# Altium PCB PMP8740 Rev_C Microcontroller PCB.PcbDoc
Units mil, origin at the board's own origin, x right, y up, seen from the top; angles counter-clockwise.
Board outline 1780 x 1140 mil, 4 copper layers (Top Layer, MidLayer1, MidLayer2, Bottom Layer), stack 90 mil thick; 19 components, 37 nets, 112 pads, 52 vias.
Unrouted connection lines stored in the file: 1.
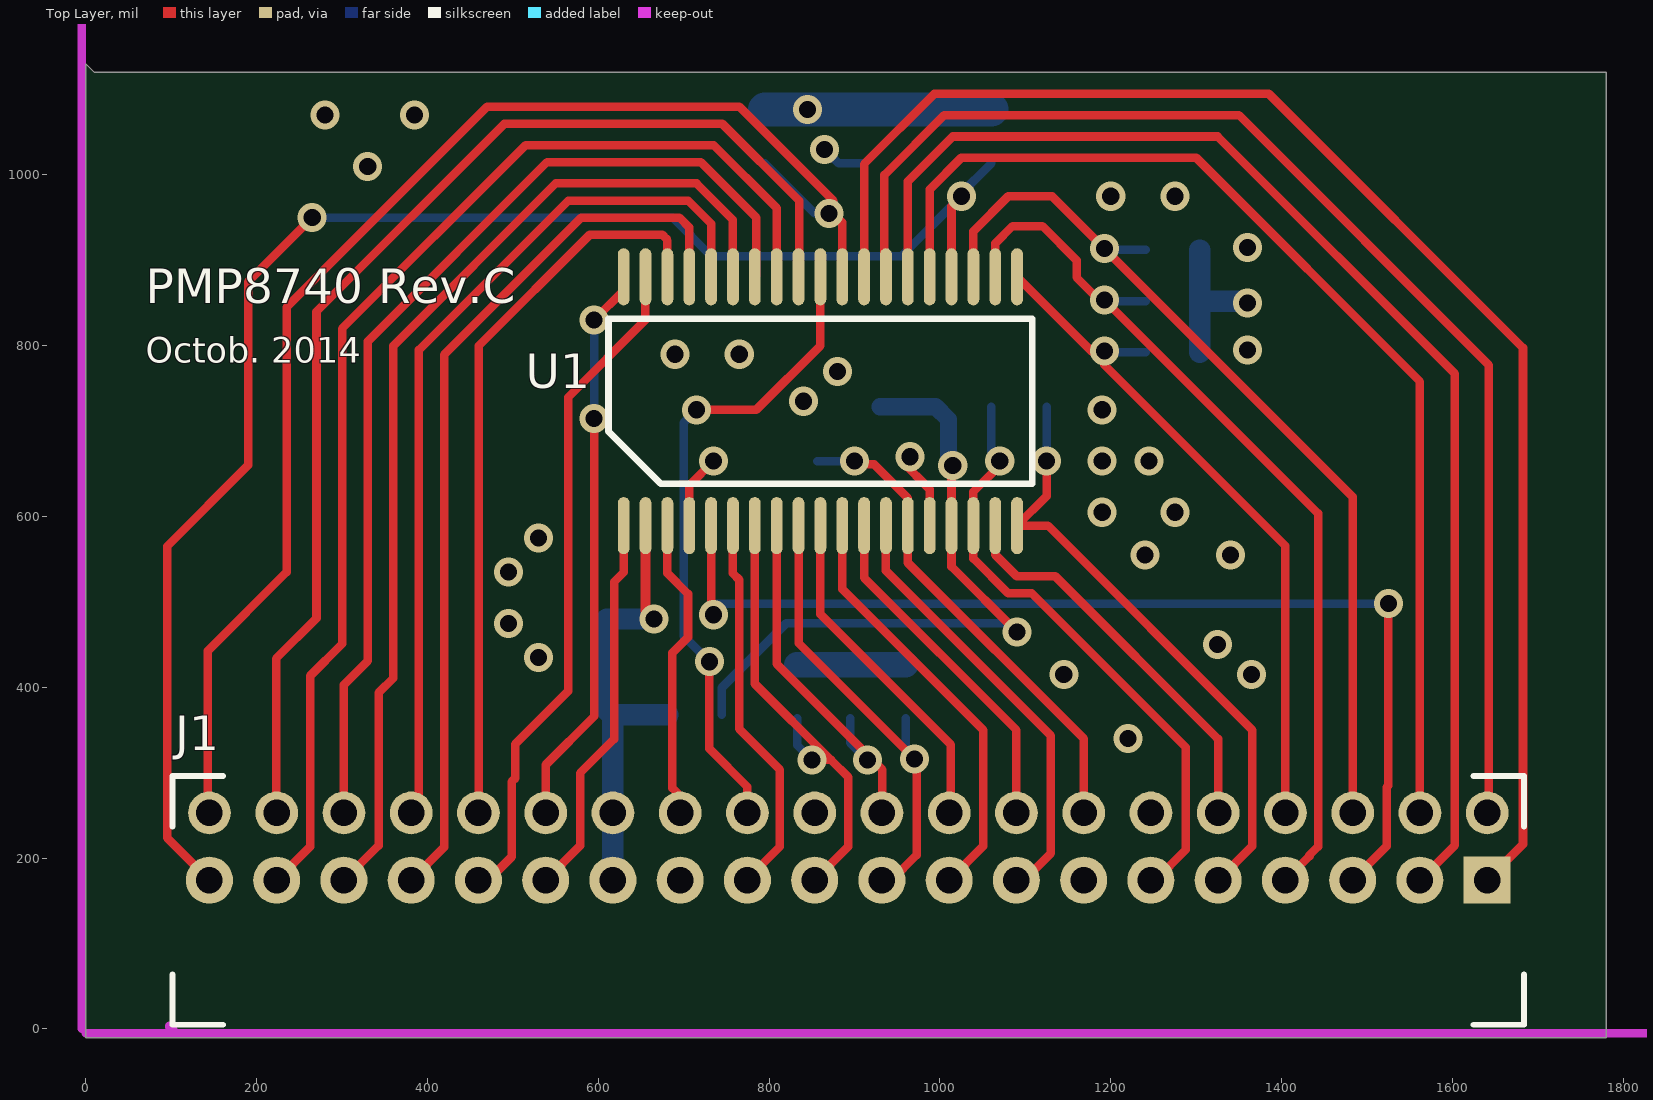
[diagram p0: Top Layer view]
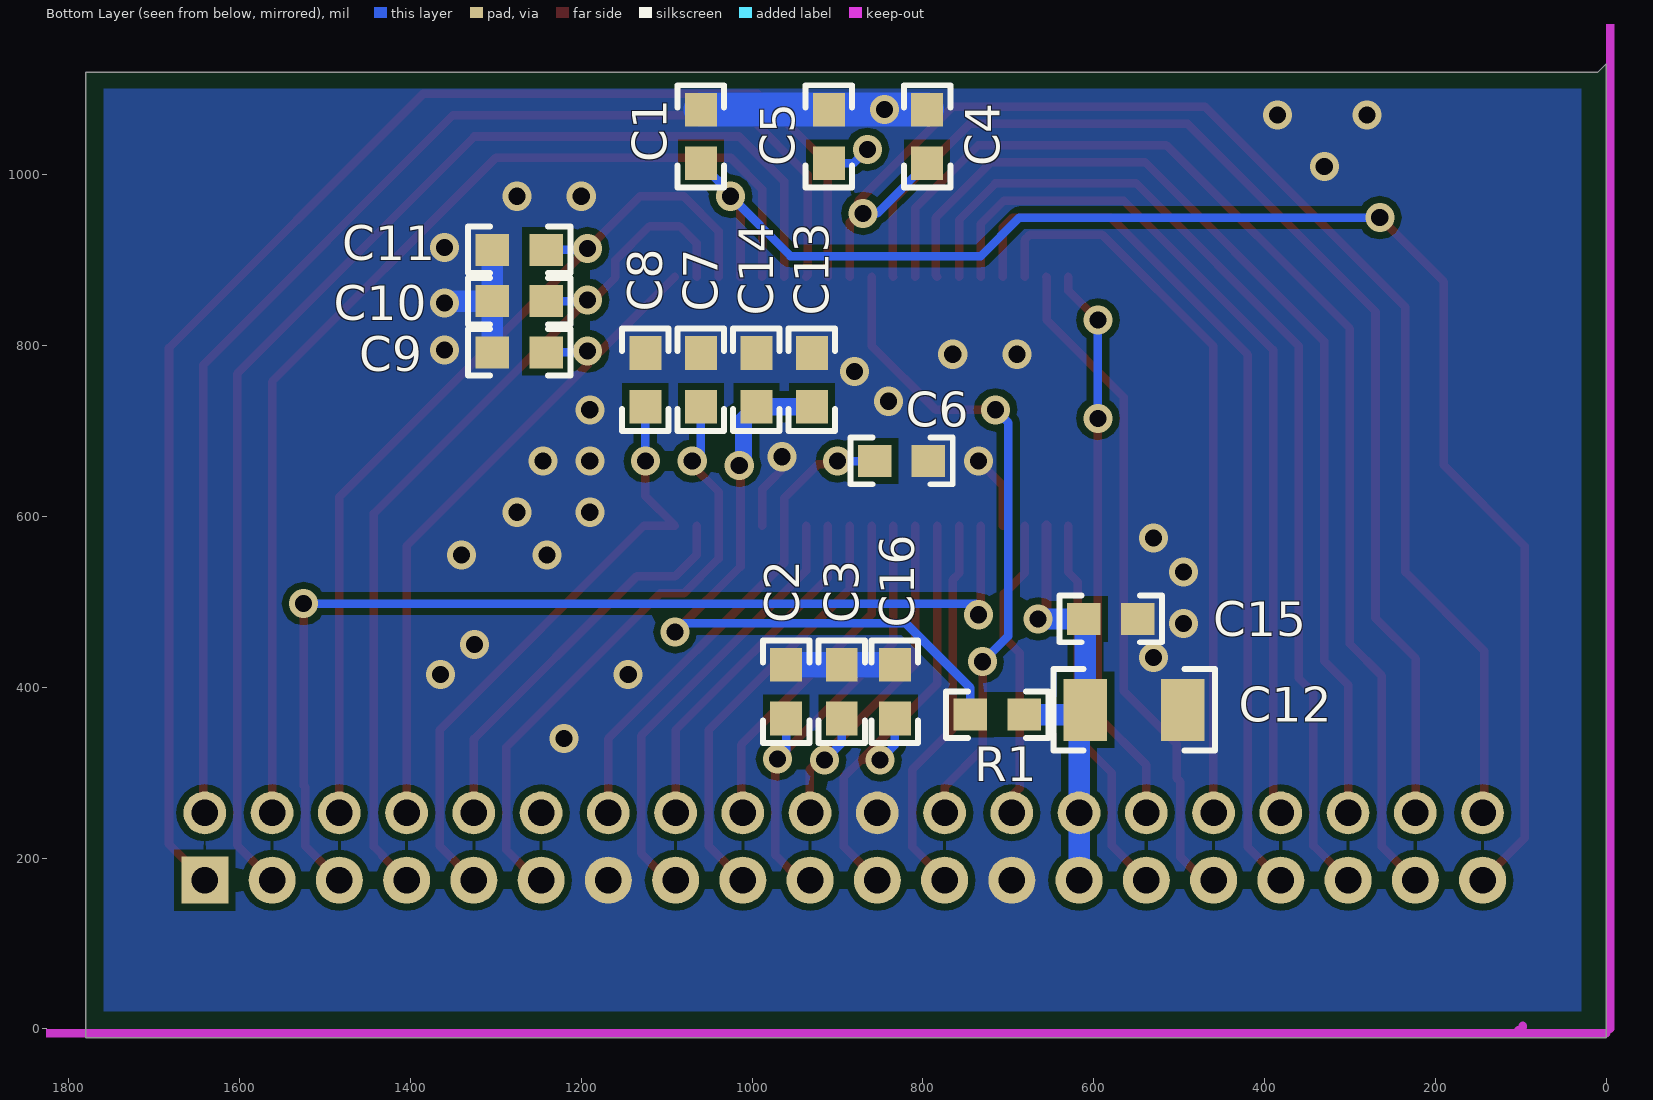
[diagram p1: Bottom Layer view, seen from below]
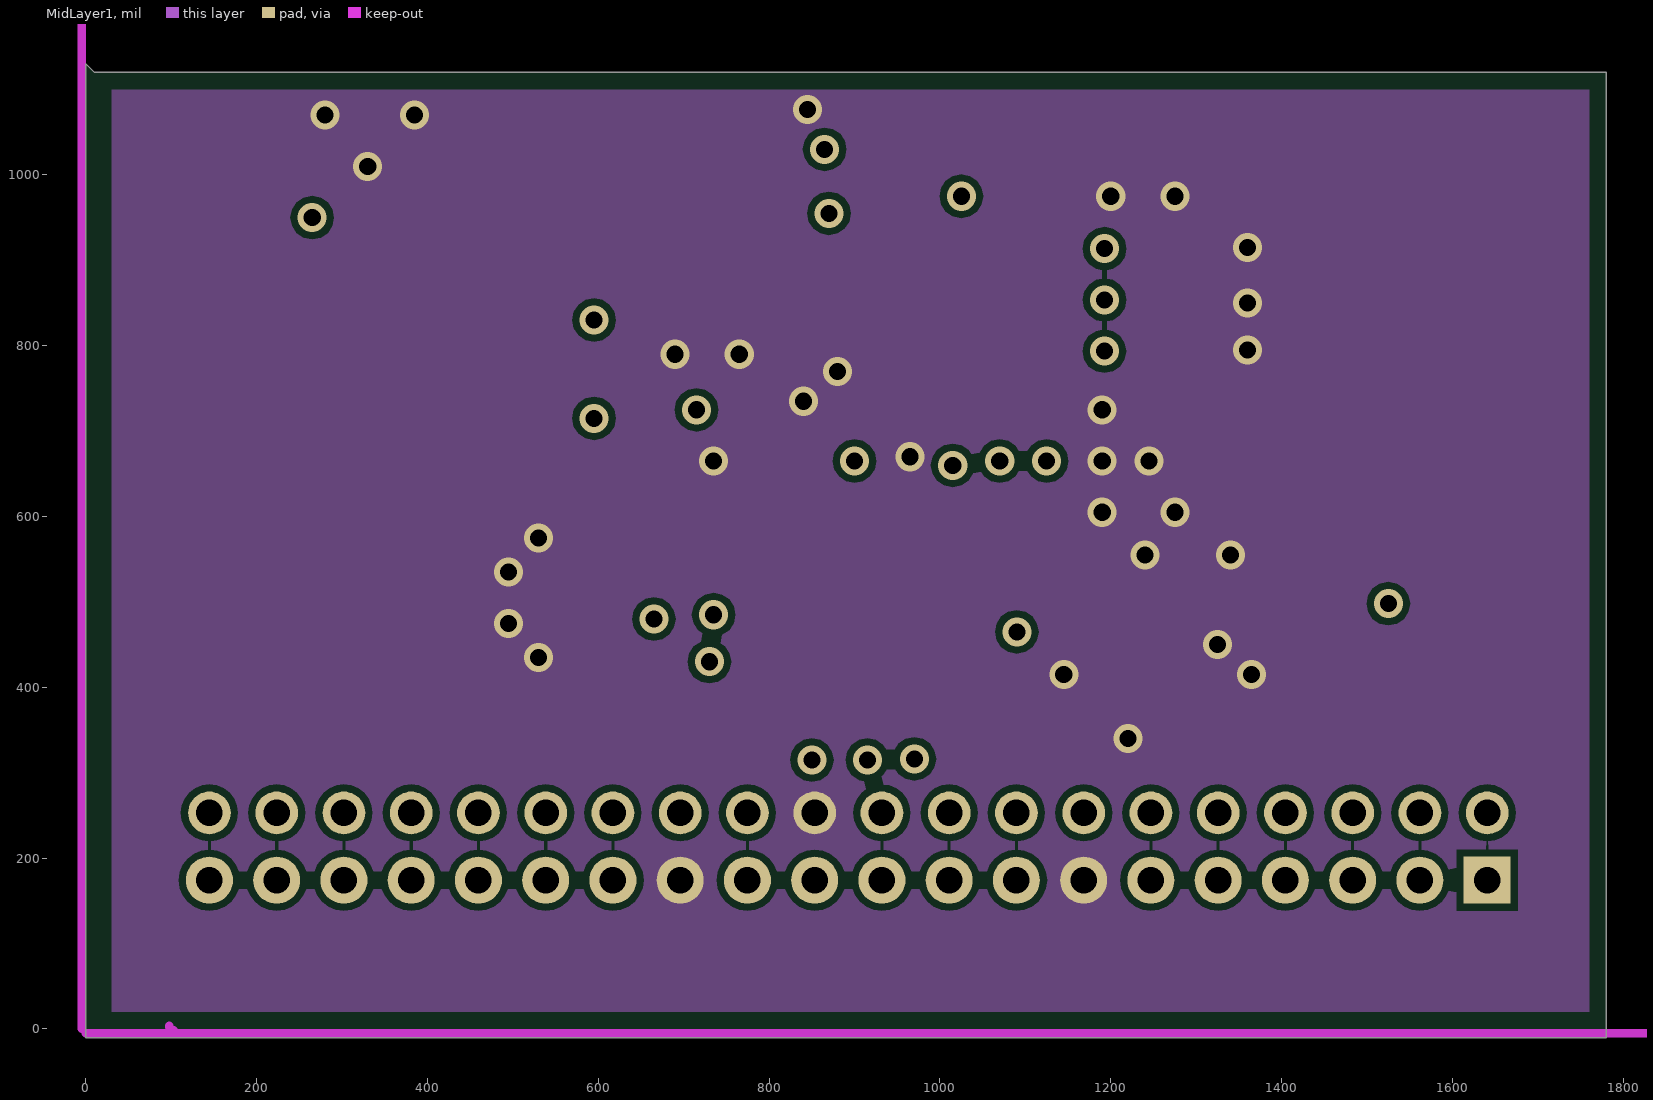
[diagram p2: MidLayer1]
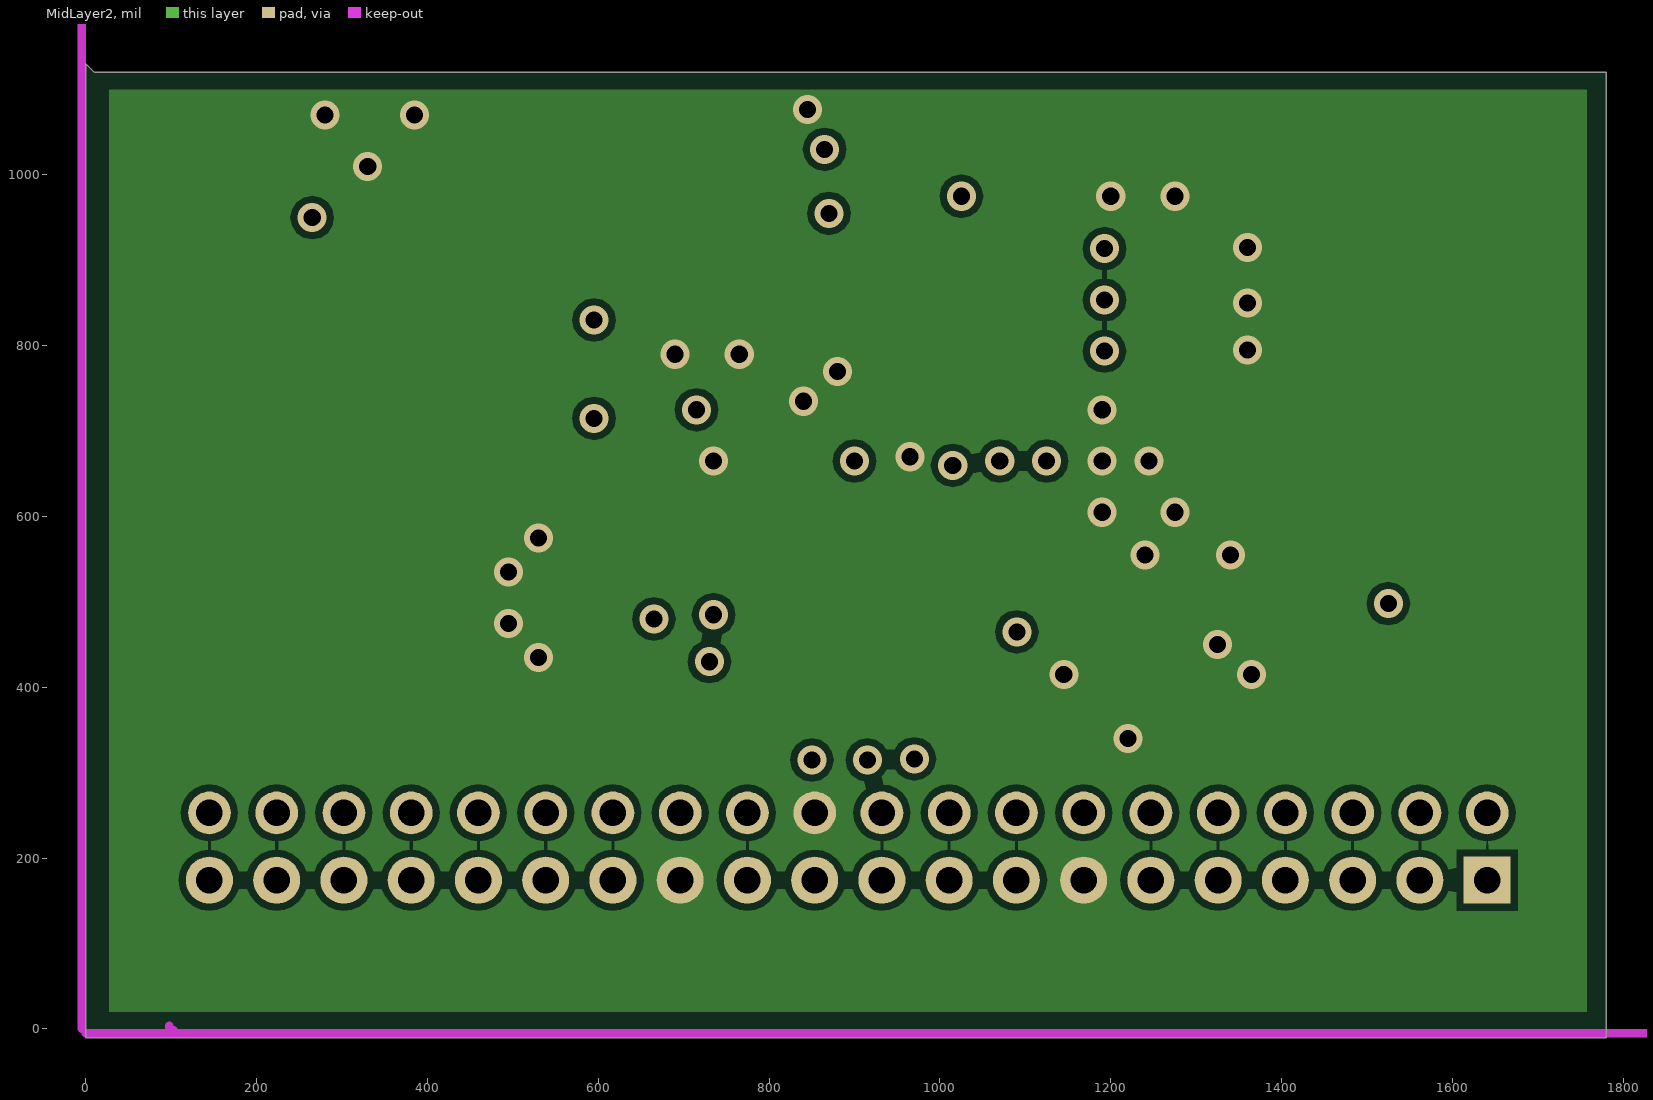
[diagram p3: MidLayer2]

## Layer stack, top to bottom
Top Layer: signal copper 1.4
Dielectric: prepreg 59.2, FR-4, Dk 4.8
MidLayer1: signal copper 1.4
Dielectric: core 12.6, FR-4, Dk 4.8
MidLayer2: signal copper 1.4
Dielectric: prepreg 12.6, FR-4, Dk 4.8
Bottom Layer: signal copper 1.4

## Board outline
0,1130 10,1120 1780,1120 1780,-10 0,-10

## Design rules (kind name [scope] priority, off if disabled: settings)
AcuteAngle [All] p1: minimum=4.50000000000000E+0001 checktracksonly=FALSE
AssemblyTestPointUsage [All] p1: valid=2
Clearance Clearance_3 [InNamedPolygon('Mid Layer 2 ground plane')] p1: gap=8
Clearance Clearance_2 [InNamedPolygon('Mid Layer 1 ground plane')] p2: gap=8
Clearance Clearance_1 [InNamedPolygon('Bottom layer ground plane')] p3: gap=8
Clearance "Clearance for GND" [InNamedPolygon('MidLayer1-No Net')] p4: gap=8
Clearance Clearance_BoardEdge_MountingHoles [OnCopper and InComponentClass('Mounting Holes') vs IsKeepOut] p5: gap=40
Clearance Clearance_BoardEdge_Poly [OnCopper and InPoly vs IsKeepOut] p6: gap=25
Clearance Clearance_BoardEdge [OnCopper and Not InComponentClass('Logo') and not InComponentClass('FiducialMark') and not InRegion(1000,500,4000,800) and Not IsKeepout vs IsKeepOut] p7: gap=75
Clearance Clearance_Poly [InPolygon] p8: gap=25
Clearance [All] p9: gap=8
ComponentClearance ComponentClearance_Logo [InComponentClass('Logo')] p1: gap=50 collisioncheckmode=3 verticalgap=10 showdistances=FALSE
ComponentClearance ComponentClearance_ScrewToNut [(HasFootprint('NY PMS 440 0025 PH')) vs (HasFootprint('Keystone_1902C'))] p2: gap=5 collisioncheckmode=3 verticalgap=10 showdistances=FALSE
ComponentClearance ComponentClearance_MountingHoles [InComponentClass('Mounting Holes')] p3: gap=250 collisioncheckmode=3 verticalgap=100000 showdistances=FALSE
ComponentClearance ComponentClearance_SmallPassives [HasFootprint('0201*') or HasFootprint('0402*') or HasFootprint('0508') or HasFootprint('0603*') or HasFootprint('0612') or HasFootprint('0805*') or HasFootprint('0815*') or HasFootprint('0830*') or HasFootprint('1206*') or HasFootprint('1210*') or HasFootprint('1808*') or HasFootprint('1812*') or HasFootprint('1825*') or HasFootprint('2010*') or HasFootprint('2220*') or HasFootprint('2225*') or HasFootprint('2512*') or HasFootprint('2728*') or HasFootprint('3518*') vs HasFootprint('0201*') or HasFootprint('0402*') or HasFootprint('0508') or HasFootprint('0603*') or HasFootprint('0612') or HasFootprint('0805*') or HasFootprint('0815*') or HasFootprint('0830*') or HasFootprint('1206*') or HasFootprint('1210*') or HasFootprint('1808*') or HasFootprint('1812*') or HasFootprint('1825*') or HasFootprint('2010*') or HasFootprint('2220*') or HasFootprint('2225*') or HasFootprint('2512*') or HasFootprint('2728*') or HasFootprint('3518*')] p4: gap=20 collisioncheckmode=3 verticalgap=10 showdistances=FALSE
ComponentClearance ComponentClearance_THtoSMT [IsThruComponent vs IsSMTComponent] p5: gap=100 collisioncheckmode=3 verticalgap=30 showdistances=FALSE
ComponentClearance ComponentClearance_THtoTH [IsThruComponent vs IsThruComponent] p6: gap=118.11 collisioncheckmode=3 verticalgap=30 showdistances=FALSE
ComponentClearance [All] p7: gap=40 collisioncheckmode=3 verticalgap=10 showdistances=FALSE
DiffPairsRouting [All] p1: maxlimit=100 minlimit=10 mostfreqgap=10 maxuncoupledlength=1000
FabricationTestPointUsage TestPointUsage [All] p1: valid=2 allowmultiple=FALSE
FabricationTestpoint Testpoint [All] p1: side=3 testpointundercomponent=TRUE minsize=40 maxsize=100 preferedsize=60 minholesize=0 maxholesize=40 preferedholesize=32 testpointgrid=1 allowsidetop=TRUE allowsidebottom=TRUE usegrid=TRUE gridtolerance=0.01
FanoutControl Fanout_LCC [IsLCC] p1: bgadir=Out bgaviamode=Centered fanoutstyle=Auto fanoutdirection=Alternating viagrid=1 // Fanout_LCC (Default Rule)
FanoutControl Fanout_BGA [IsBGA] p2: bgadir=Out bgaviamode=Centered fanoutstyle=Auto fanoutdirection=Alternating viagrid=1 // Fanout_BGA (Default Rule)
FanoutControl Fanout_Default [All] p4: bgadir=Out bgaviamode=Centered fanoutstyle=Auto fanoutdirection=Alternating viagrid=1 // Fanout_Default (Default Rule)
FanoutControl Fanout_Small [(CompPinCount < 5)] p5: bgadir=Out bgaviamode=Centered fanoutstyle=Auto fanoutdirection=OutThenIn viagrid=1 // Fanout_Small (Default Rule)
HoleSize [All] p1: absolutevalues=TRUE maxlimit=251 minlimit=8 maxpercent=80.000 minpercent=20.000
MinimumAnnularRing MinimumAnnularRing_ThermalPadVias [IsVia and InAnyComponent] p1: minimumring=5.91
MinimumAnnularRing [All] p2: minimumring=9
MinimumSolderMaskSliver MinimumSolderMaskSliver_Logo [InComponentClass('Logo') vs InComponentClass('Logo')] p1: minsoldermaskwidth=0.7
MinimumSolderMaskSliver [All] p2: minsoldermaskwidth=3.94
PlaneConnect [All] p1: planeconnectstyle=Relief reliefexpansion=10 reliefentries=4 reliefconductorwidth=10 reliefairgap=10
PolygonConnect PolygonConnect_6 [All vs IsNamedPolygon('Mid Layer 2 ground plane')] p1: connectstyle=Direct reliefconductorwidth=10 reliefentries=4 polygonreliefangle="90 Angle" airgapwidth=10
PolygonConnect PolygonConnect_5 [All vs IsNamedPolygon('Mid Layer 1 ground plane')] p2: connectstyle=Direct reliefconductorwidth=10 reliefentries=4 polygonreliefangle="90 Angle" airgapwidth=10
PolygonConnect PolygonConnect_4 [All vs IsNamedPolygon('Bottom layer ground plane')] p3: connectstyle=Direct reliefconductorwidth=10 reliefentries=4 polygonreliefangle="90 Angle" airgapwidth=10
PolygonConnect PolygonConnect_3 [All vs IsNamedPolygon('MidLayer1-No Net')] p4: connectstyle=Direct reliefconductorwidth=10 reliefentries=4 polygonreliefangle="90 Angle" airgapwidth=10
PolygonConnect PolygonConnect_2 [All vs IsNamedPolygon('MidLayer1-No Net')] p5: connectstyle=Direct reliefconductorwidth=10 reliefentries=4 polygonreliefangle="90 Angle" airgapwidth=10
PolygonConnect PolygonConnect_1 [All vs IsNamedPolygon('MidLayer1-No Net')] p6: connectstyle=Direct reliefconductorwidth=10 reliefentries=4 polygonreliefangle="90 Angle" airgapwidth=10
PolygonConnect [All] p7: connectstyle=Relief reliefconductorwidth=10 reliefentries=4 polygonreliefangle="90 Angle" airgapwidth=10
RoomDefinition "PMP8740 Rev_C 2KW BC Microcontroller Schematic" [InComponentClass('PMP8740 Rev_C 2KW BC Microcontroller Schematic')] p1: confinementstyle=ConfineIn formatcopy=TRUE lockcomponents=FALSE outline 4998,76 8798,76 8798,1756 4998,1756
RoutingVias ThermalPadVias [IsVia and InAnyComponent] p1: holewidth=7.87 width=19.68 viastyle="Through Hole" minholewidth=7.87 minwidth=19.68 maxholewidth=12.99 maxwidth=23.62
RoutingVias [All] p2: holewidth=16 width=34 viastyle="Through Hole" minholewidth=16 minwidth=34 maxholewidth=16 maxwidth=34
SMDToCorner [All] p1: distance=30000
SilkToSilkClearance [All] p1: silktosilkclearance=5
SilkscreenOverComponentPads [All] p1: minsilkscreentomaskgap=5
SolderMaskExpansion [All] p1: expansion=1.97
Width [All] p1: maxlimit=100 minlimit=6 preferedwidth=10 checkconnectedcopper=TRUE
14 further rules are at their usual default settings.

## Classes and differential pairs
component class "PMP8740 Rev_C 2KW BC Microcontroller Schematic": C1 C2 C3 C4 C5 C6 C8 C9 C10 C11 C12 C13 C14 C15 C16 J1 R1 U1

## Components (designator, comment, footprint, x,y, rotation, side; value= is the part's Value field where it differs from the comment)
C1 "C1608X7R1H104K" 0603 1060,1045 r90 bottom
C2 "C1608X7R1H473K" 0603 960,395 r90 bottom
C3 "C1608X7R1H104K" 0603 895,395 r90 bottom
C4 "C1608X7R1E105K080AB" 0603 795,1045 r90 bottom
C5 "C1608X7R1H104K" 0603 910,1045 r90 bottom
C6 "C1608X7R1H104K" 0603 825,665 r180 bottom
C7 "C1608X7R1H103K" 0603 1060,760 r90 bottom
C8 "C1608X7R1H103K" 0603 1125,760 r90 bottom
C9 "C1608X7R1H103K" 0603 1272.68,792.16 r0 bottom
C10 "C1608X7R1H103K" 0603 1272.68,852.16 r0 bottom
C11 "C1608X7R1H103K" 0603 1272.68,912.16 r0 bottom
C12 "C3216X7R1A106M" 1206 552.68,373.61 r180 bottom
C13 "C1608X7R1E105K080AB" 0603 930,760 r90 bottom
C14 "C1608X7R1H104K" 0603 995,760 r90 bottom
C15 "C1608X7R1H104K" 0603 580,480 r180 bottom
C16 "C1608C0G1H102J" 0603 832.68,395 r90 bottom
J1 "NPPN202FJFN-RC" HEADER_NPPN202FJFN-RC 892.68,213.61 r0 top
R1 "CRCW060333R2FKEA" 0603 713,368 r180 bottom
U1 "MSP430F2252TDA" DA0038A_N 860,735 r90 top

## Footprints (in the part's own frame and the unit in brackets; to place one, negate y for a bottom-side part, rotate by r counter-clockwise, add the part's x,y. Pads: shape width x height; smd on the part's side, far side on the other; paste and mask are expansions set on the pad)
0603 [mm] "0603 from SM-752 data"
  rect 1x0.95 smd: 1(-0.8,0) 2(0.8,0)
  silkscreen extent -1.52,-0.69 1.52,0.69, body extent -0.87,-0.47 0.87,0.47, height 0.85
1206 [mm] "1206 from SM-752 data"
  rect 1.3x1.85 smd: 1(-1.45,0) 2(1.45,0)
  silkscreen extent -2.4,-1.21 2.4,1.21, body extent -1.7,-0.9 1.7,0.9, height 1.35
DA0038A_N [mm] "TSOP, 38-Leads, Body 12.6x6.2mm (max), Pitch 0.65mm, IPC Medium Density"
  oval 1.7x0.35 smd: 1(-3.7,5.85) 2(-3.7,5.2) 3(-3.7,4.55) 4(-3.7,3.9) 5(-3.7,3.25) 6(-3.7,2.6) 7(-3.7,1.95) 8(-3.7,1.3) 9(-3.7,0.65) 10(-3.7,0) 11(-3.7,-0.65) 12(-3.7,-1.3) 13(-3.7,-1.95) 14(-3.7,-2.6) 15(-3.7,-3.25) 16(-3.7,-3.9) 17(-3.7,-4.55) 18(-3.7,-5.2) 19(-3.7,-5.85) 20(3.7,-5.85) 21(3.7,-5.2) 22(3.7,-4.55) 23(3.7,-3.9) 24(3.7,-3.25) 25(3.7,-2.6) 26(3.7,-1.95) 27(3.7,-1.3) 28(3.7,-0.65) 29(3.7,0) 30(3.7,0.65) 31(3.7,1.3) 32(3.7,1.95) 33(3.7,2.6) 34(3.7,3.25) 35(3.7,3.9) 36(3.7,4.55) 37(3.7,5.2) 38(3.7,5.85)
  silkscreen extent -2.45,-6.3 2.45,6.3, body extent -4.17,-6.3 4.11,6.3, height 1.2
HEADER_NPPN202FJFN-RC [mm] "Sullins, Header 20x2 ,2mm Pitch"
  rect 1.4x1.4 hole 0.787: 1(19,-1)
  round 1.27 hole 0.787: 2(19,1) 4(17,1) 6(15,1) 8(13,1) 10(11,1) 12(9,1) 14(7,1) 16(5,1) 18(3,1) 20(1,1) 22(-1,1) 24(-3,1) 26(-5,1) 28(-7,1) 30(-9,1) 32(-11,1) 34(-13,1) 36(-15,1) 38(-17,1) 40(-19,1)
  round 1.4 hole 0.787: 3(17,-1) 5(15,-1) 7(13,-1) 9(11,-1) 11(9,-1) 13(7,-1) 15(5,-1) 17(3,-1) 19(1,-1) 21(-1,-1) 23(-3,-1) 25(-5,-1) 27(-7,-1) 29(-9,-1) 31(-11,-1) 33(-13,-1) 35(-15,-1) 37(-17,-1) 39(-19,-1)
  silkscreen extent -20.1,-5.3 20.1,2.1, body extent -20.06,-5.26 20.06,2.06, height 4.92

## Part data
C1 C3 C5 C6 C14 C15: "CAP, CERM, 0.1uF, 50V, +/-10%, X7R, 0603"
C2: "CAP, CERM, 0.047 µF, 50 V, +/- 10%, X7R, 0603"
C4 C13: "CAP, CERM, 1uF, 25V, +/-10%, X7R, 0603"
C7 C8 C9 C10 C11: "CAP, CERM, 0.01uF, 50V, +/-10%, X7R, 0603"
C12: "CAP, CERM, 10uF, 10V, +/-20%, X7R, 1206"
C16: "CAP, CERM, 1000pF, 50V, +/-5%, C0G/NP0, 0603"
J1: "Receptacle, 2mm, 20x2, R/A, TH"
R1: "RES, 33.2 ohm, 1%, 0.1W, 0603"
U1: "MIXED SIGNAL MICROCONTROLLER, DA0038A"

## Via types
v1: diameter 34, hole 20, Top Layer to Bottom Layer, 52 vias

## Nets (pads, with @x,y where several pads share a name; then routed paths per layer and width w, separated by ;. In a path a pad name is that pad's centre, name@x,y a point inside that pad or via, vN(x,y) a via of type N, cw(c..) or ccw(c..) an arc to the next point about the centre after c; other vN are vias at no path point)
+3V45: C12.1 C15.1 J1.27 J1.28 R1.2 U1.2 | length 541.5
  Top Layer w12: U1.2 655.28,489.72 v1(665,480)
  Bottom Layer w25: C15.1@609.77,479.77 C12.1 C12.1@615.38,368 ; C15.1 v1(665,480) ; J1.27 J1.28 617.09,366.29 C12.1@615.38,368 ; R1.2 C12.1@615.38,368
"BACKLIGHT P1.0": J1.37 U1.31 | length 1386.5
  Top Layer w10: J1.37 262.68,213.54 262.68,413.61 300,450.93 300,820 515,1035 735,1035 808.82,961.18 U1.31
"CLOCK TEST/SBWTCK": J1.29 U1.1 | length 453.2
  Top Layer w10: J1.29 578.68,214.57 578.68,299.61 618.43,339.36 618.43,523.43 630,535 630,589.02 U1.1
"D4(D0) P1.7": J1.30 U1.38 | length 665.5
  Top Layer w10: J1.30 538.35,309.28 595,365.93 v1(595,715) ; v1(595,830) 629.68,864.68 U1.38
  Bottom Layer w10: v1(595,715) v1(595,830)
"D5(D1) P1.6": J1.31 U1.37 | length 794.3
  Top Layer w10: J1.31 471.31,174.24 498.68,201.61 498.68,289.61 502.68,293.61 502.68,333.61 564.53,395.47 564.53,739.53 655,830 655,880.39 U1.37
"D6(D2) P1.5": J1.32 U1.36 | length 867.8
  Top Layer w10: J1.32 460.16,253.54 460.16,800.16 590,930 675,930 680,925 680,923.98 680.87,923.11 U1.36
"D7(D3) P1.4": J1.33 U1.35 | length 1047.3
  Top Layer w10: J1.33 419.68,213.05 419.68,789.68 580,950 695,950 706.46,938.54 U1.35
"DATA_I/O RST/NMI": C16.1 J1.21 U1.7 | length 554.9
  Top Layer w10: U1.7 783.23,404.31 872.53,315 ; v1(850,315) 872.53,315 ; J1.21 892.68,213.61 892.68,294.85 872.53,315
  Bottom Layer w10: C16.1 832.68,332.32 v1(850,315)
"E P1.3": J1.34 U1.34 | length 1031.3
  Top Layer w10: J1.34@382.68,254.79 390,262.11 390,795 565,970 705,970 732.05,942.95 U1.34
"ENA_FB P4.7": J1.4 U1.24 | length 1305.2
  Top Layer w10: U1.24 987.95,982.95 1025,1020 1300,1020 1561.97,758.03 J1.4
GND-S: C1.2 C2.2 C3.2 C4.2 C5.2 C6.2 C7.2 C8.2 C9.2 C10.2 C11.2 C12.2 C13.2 C14.2 C15.2 C16.2 J1.13 J1.22 J1.25 U1.4 U1.15 | length 757.9
  Top Layer w10: U1.4 706.46,636.46 v1(735,665) ; v1@965,660 960,665 955,665 987.95,632.05 U1.15
  Bottom Layer w25: C9.2 C10.2 ; C11.2 C10.2 ; v1(1360,850) 1357.84,852.16 C10.2
  Bottom Layer w30: C16.2 C3.2 C2.2
  Bottom Layer w40: C4.2 C5.2 C1.2
  other v1: 1220,340 1145,415 1365,415 530,435 1325,450 495,475 495,535 1240,555 1340,555 530,575 1190,605 1275,605 1190,665 1245,665 965,670 1190,725 840.31,735 880,770 690,790 765,790 1360,795 1360,915 1200,975 1275,975 330,1010 280,1070 385,1070 845,1076.5
"INRUSH_RELAY P2.6": J1.23 U1.6 | length 453.7
  Top Layer w10: U1.6 757.64,533.36 765,526 765,351.29 812.68,303.61 812.68,213.61 774.57,175.5 J1.23
"IOUT FB P3.7": C4.1 J1.40 U1.28 | length 1590.4
  Top Layer w10: J1.40 142.68,254.95 142.68,442.68 235,535 235,845 470,1080 765,1080 875,970 875,955 885.59,944.41 U1.28
  Bottom Layer w10: C4.1 v1@853.5,955
  other v1: 870,955
"LED_GREEN P3.0": J1.17 U1.11 | length 500
  Top Layer w10: U1.11 885.59,515.09 1050.68,350 1050.68,214.13 J1.17
"LED_RED P3.2": J1.15 U1.13 | length 516.8
  Top Layer w10: U1.13 936.77,536.5 1129.68,343.59 1129.68,205.61 1098.31,174.24 J1.15
"LED_YELLOW P3.1": J1.16 U1.12 | length 410.2
  Top Layer w10: U1.12 911.18,528.35 1089.53,350 J1.16
NetC13_1: C13.1 C14.1 R1.1 U1.16 | length 795.9
  Top Layer w10: v1@1005,665 1010,660 v1(1015,660) ; v1@1013.54,660 U1.16 1013.54,541.46 v1(1090,465)
  Bottom Layer w10: R1.1 744.5,399.5 820,475 1080,475 v1(1090,465)
  Bottom Layer w20: C13.1 C14.1 1010,713.5 1010,660 v1(1015,660)
P2.7: J1.5 U1.5 | length 1246.6
  Top Layer w10: v1@732.05,485 U1.5 ; J1.5 1523,214.01 1523,283 1525,285 v1(1525,498)
  Bottom Layer w10: v1(735,485) 735,495 738,498 v1(1525,498)
"PFC_ON P2.5": J1.26 U1.3 | length 351.8
  Top Layer w10: U1.3 680.87,533.56 705,509.42 705,458.69 686.75,440.44 686.75,282.07 J1.26@705.83,262.98
"PG_PFC P2.1": C2.1 J1.19 U1.9 | length 568.4
  Top Layer w10: U1.9 834.41,451.88 972.68,313.61 972.68,203.61 943.31,174.24 J1.19
  Bottom Layer w10: C2.1 960,326.29 972.68,313.61 974.07,315 979.53,315 978.24,316.29 v1(970,316.29)
"PRE-CHARGE P2.2": J1.18 U1.10 | length 400.4
  Top Layer w10: U1.10 860,485.63 1012.68,332.95 1012.68,254.87 J1.18
"PWM_IREF P2.3": J1.24 U1.29 | length 769.3
  Top Layer w10: v1(715,725) 785,725 860,800 U1.29 ; v1(730,430) 730,328 774.57,283.43 J1.24
  MidLayer2 w10: J1.24 J1.24@777,255.41
  Bottom Layer w10: v1(715,725) 700,710 700,460 v1(730,430)
"PWM_VREF P2.4": J1.38 U1.30 | length 1389.9
  Top Layer w10: J1.38 222.68,253.69 222.68,433.61 270,480.93 270,840 490,1060 745,1060 835,970 835,881.26 U1.30
"R/W P1.2": J1.35 U1.33 | length 1210.4
  Top Layer w10: J1.35 342.68,214.8 342.68,393.61 360,410.93 360,800 550,990 715,990 757.64,947.36 U1.33
"REVERSE POLARITY P3.3": C6.1 J1.14 U1.14 | length 577.8
  Top Layer w10: v1(900,665) 904,661 923,661 962.36,621.64 U1.14 962.36,545.91 1168.27,340 J1.14
  Bottom Layer w10: C6.1 v1(900,665)
"RS P1.1": J1.36 U1.32 | length 1202.5
  Top Layer w10: J1.36 302.13,403.06 330,430.93 330,805 540,1015 720,1015 785,950 785,882.44 U1.32
"RX P3.5": J1.2 U1.26 | length 1503.1
  Top Layer w10: U1.26 935,882.44 935,1000 1005,1070 1350,1070 1642.68,777.32 1642.68,254.95 J1.2
"S1 (ESC) P4.5": C11.1 J1.6 U1.22 | length 1079.5
  Top Layer w10: U1.22 1039.13,934.13 1080,975 1131.29,975 v1(1192.68,913.61) 1483.23,623.06 J1.6
  Bottom Layer w10: v1(1192.68,913.61) 1194.14,912.16 C11.1
"S2 (-) P4.4": C10.1 J1.7 U1.21 | length 1070.8
  Top Layer w10: U1.21 1064.72,919.72 1085,940 1120,940 1160,900 1160,880 1186.39,853.61 v1(1192.68,853.61) 1442.68,603.61 1442.68,213.61 1432.68,203.61 1432.68,202.43 J1.7
  Bottom Layer w10: v1(1192.68,853.61) 1194.14,852.16 C10.1
"S3 (+) P4.3": C9.1 J1.8 U1.20 | length 816
  Top Layer w10: U1.20 1177.37,793.61 v1(1192.52,793.61) 1192.52,777.48 1404.49,565.51 J1.8
  Bottom Layer w10: v1(1192.52,793.61) 1193.98,792.16 C9.1
"S4 (ENTER) P4.2": C8.1 J1.9 U1.19 | length 720.3
  Top Layer w10: v1(1125,665) 1125,624.02 U1.19 1126.35,589.33 1365.68,350 1365.68,214.17 J1.9
  Bottom Layer w10: v1(1125,665) C8.1
"SPEED_READING P4.0": C7.1 J1.11 U1.17 | length 724.7
  Top Layer w10: v1@1060,665 v1(1070,665) ; v1@1072.5,662.5 1039.13,629.13 U1.17 1039.13,550.87 1080,510 1107.68,510 1287.68,330 1287.68,209.61 1252.31,174.24 J1.11
  Bottom Layer w10: C7.1 1060,665 v1(1070,665)
"SPEED_SET P4.1": J1.10 U1.18 | length 471.3
  Top Layer w10: U1.18 1064.72,555.28 1090,530 1135,530 1325,340 1325.75,340 J1.10
"TEMP-1 P2.0": C3.1 J1.20 U1.8 | length 449.2
  Top Layer w10: U1.8 808.82,427.48 v1@918.15,318.15 ; v1(915,315) v1@918.15,318.15 ; J1.20 932.68,253.61 932.68,303.61 v1@918.15,318.15
  Bottom Layer w10: C3.1 895,335 v1(915,315)
"TX P3.4": J1.3 U1.25 | length 1498.8
  Top Layer w10: U1.25 962.36,992.36 1015,1045 1325,1045 1602.68,767.32 1602.68,214.95 J1.3
"VAC_IN P4.6": C1.1 J1.39 U1.23 | length 1827.9
  Top Layer w10: J1.39 95,223.89 95,565 190,660 190,875 v1(265,950) ; U1.23 1013.54,963.54 v1(1025,975)
  Bottom Layer w10: v1(265,950) 687.05,950 732.05,905 955,905 v1(1025,975) 1023.25,976.75 C1.1
"VOUT FB P3.6": C5.1 J1.1 U1.27 | length 1753.2
  Top Layer w10: U1.27 911.18,1012.64 993.54,1095 1385,1095 1682.68,797.32 1682.68,216.21 J1.1
  Bottom Layer w10: v1(865,1030) 881.5,1013.5 C5.1
pads on no net: J1.12

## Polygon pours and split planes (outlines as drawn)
GND-S on Bottom Layer "Bottom layer ground plane" (solid, pour order 8): 29.26,1100.74 1759.26,1100.74 1759.26,20.74 29.26,20.74
GND-S on MidLayer1 "Mid Layer 1 ground plane" (solid, pour order 9): 30,1100 1760,1100 1760,20 30,20
GND-S on MidLayer2 "Mid Layer 2 ground plane" (solid, pour order 10): 27.37,1100 1757.37,1100 1757.37,20 27.37,20

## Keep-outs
Keep-Out Layer:
  lines w10: -5,0 -5,3450 ; 0,-5 4950,-5 ; -5,3450 cw(c0,3450) 0,3455 ; -5,3450 cw(c0,3450) 0,3455 ; -5,3450 cw(c0,3450) 0,3455 ; -5,3450 cw(c0,3450) 0,3455 ; -5,3450 cw(c0,3450) 0,3455 ; -5,3450 cw(c0,3450) 0,3455 ; 0,3455 4950,3455 ; 97.68,3.61 ccw(c102.68,3.61) 102.68,-1.39 ; 97.68,3.61 ccw(c102.68,3.61) 102.68,-1.39 ; 97.68,3.61 ccw(c102.68,3.61) 102.68,-1.39 ; 97.68,3.61 ccw(c102.68,3.61) 102.68,-1.39 ; 97.68,3.61 ccw(c102.68,3.61) 102.68,-1.39 ; 97.68,3.61 ccw(c102.68,3.61) 102.68,-1.39 ; 4950,-5 ccw(c4950,0) 4955,0 ; 4950,-5 ccw(c4950,0) 4955,0 ; 4950,-5 ccw(c4950,0) 4955,0 ; 4950,-5 ccw(c4950,0) 4955,0 ; 4950,-5 ccw(c4950,0) 4955,0 ; 4950,-5 ccw(c4950,0) 4955,0 ; 4950,3455 cw(c4950,3450) 4955,3450 ; 4950,3455 cw(c4950,3450) 4955,3450 ; 4950,3455 cw(c4950,3450) 4955,3450 ; 4950,3455 cw(c4950,3450) 4955,3450 ; 4950,3455 cw(c4950,3450) 4955,3450 ; 4950,3455 cw(c4950,3450) 4955,3450 ; 4955,0 4955,3450
  text ".Layer_Name" at 577,-858.49 h60

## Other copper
Top Layer:
  text "©" at 3000,3280 h105
  text ".CopyrightYear" at 3164,3280 h60
  text "TI" at 3440,3280 h60
  text ".Layer_Name" at 577,-858.49 h60
Bottom Layer:
  text "UL94V-0" at 4040,3280 h60
  text ".Layer_Name" at 577,-858.49 h60

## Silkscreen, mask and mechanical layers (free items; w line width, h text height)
Top Overlay:
  text "This document can handle board shapes up to 7.9in x 10in, although" at 140,7015 h60
  text "our panel vendors top out at 7in x 10in." at 140,6890.94 h60
  text "To re-size the board shape, do the following:" at 195,6766.88 h60
  text "Select lines on M1 Board Outline and delete (easy in single layer mode...shift+s)" at 255,6642.82 h60
  text "Draw a rectangle using lines (example will be for a 4\" x 6\" board" at 255,6518.76 h60
  text "Enter Place Line mode (keyboard pl)" at 465,6394.71 h60
  text "keyboard jo to jump to origin, hit enter" at 465,6270.65 h60
  text "keyboard jl to jump to location, set x to 6000, hit enter twice" at 465,6146.59 h60
  text "keyboard jl to jump to location, set x to 6000 and y to 4000, hit enter twice" at 465,6022.53 h60
  text "keyboard jl to jump to location, set x to 0 and y to 4000, hit enter twice" at 465,5898.47 h60
  text "keyboard jo to jump to origin, hit enter" at 465,5774.41 h60
  text "Hit ESC twice to exit place line mode" at 465,5650.35 h60
  text "Select lines on M1 Board Outline" at 255,5506.3 h60
  text "Menu Design|Board Shape|Define from Selected Objects (keyboard dsd)" at 255,5402.24 h60
  text "To define a Keep-Out that mirrors the board outline:" at 140,5278.18 h60
  text "Menu Design|Board Shape|Create Primitives From Board Shape (keyboard dsp)" at 255,5154.12 h60
  text "Set the Keep-Out Layer as the layer, set width as preferred" at 465,5030.06 h60
  text "Ensure Route Tool Outline is selected, hit enter" at 465,4906 h60
  text "If you re-size the board, don't forget to move the drill table strings on the" at 140,4583 h60
  text "Drill Drawing Layer...they should be just to the right of your board shape" at 333,4477 h60
  text ".PCB_Rev" at 2760,3290 h60
  text ".PRJ_Number" at 2260,3280 h60
  text "PMP8740 Rev.C" at 70,850 h40
  text "Octob. 2014" at 70,780 h30
  text ".Layer_Name" at 577,-858.49 h60
Bottom Overlay:
  text ".Layer_Name" at 577,-858.49 h60
Top Paste:
  text ".Layer_Name" at 577,-858.49 h60
Bottom Paste:
  text ".Layer_Name" at 577,-858.49 h60
Top Solder:
  text ".Layer_Name" at 577,-858.49 h60
  text ".Layer_Name" at 577,-858.49 h60
Bottom Solder:
  text ".Layer_Name" at 577,-858.49 h60
Drill Guide:
  text ".Layer_Name" at 577,-858.49 h60
M1 Board Outline:
  lines w10: 0,0 0,3450 4950,3450 4950,0 0,0
  text ".Layer_Name" at 577,-858.49 h60
M2 Board Dimensions:
  rectangle: -0.5,-285.5 124.5,-160.5
  rectangle: 124.5,-410.5 499.5,-285.5
  lines w7: -0.5,-285.5 999.5,-285.5 ; 124.5,-410.5 124.5,-160.5 ; 249.5,-410.5 249.5,-160.5 ; 499.5,-410.5 499.5,-160.5 ; 749.5,-410.5 749.5,-160.5 ; -0.5,-410.5 999.5,-410.5 999.5,-160.5 -0.5,-160.5 -0.5,-410.5
  lines w10: -0.5,-475.5 -0.5,-455.5 ; 59.5,-485.5 -0.5,-465.5 ; 59.5,-445.5 -0.5,-465.5 ; 223.58,-465.5 -0.5,-465.5 ; 775.42,-465.5 999.5,-465.5 ; 939.5,-485.5 999.5,-465.5 ; 939.5,-445.5 999.5,-465.5 ; 999.5,-475.5 999.5,-455.5
  text "1000 (mil)" at 233.58,-501.49 h60
  text ".Layer_Name" at 577,-858.49 h60
M3 3D STEP Top:
  text ".Layer_Name" at 577,-858.49 h60
M4 3D STEP Bottom:
  text ".Layer_Name" at 577,-858.49 h60
M5 Assembly Top:
  lines w10: -292,-930.17 6308,-930.17 ; -292,-726.83 6310,-726.83 ; -292,-523.5 -292,-1133.5 3713,-1133.5 6310,-1133.5 6310,-523.5 -291.5,-523.5 -291.5,-1133.5 1284,-1133.5 ; 2173,-1133.5 2173,-523.5 ; 3440,-726.83 3440,-523.5 ; 4280,-726.83 4280,-523.5 ; 4902,-1140 4902,-937.17
  text "COMPONENTS MARKED 'DNP' SHOULD NOT BE POPULATED." at 1153.5,-318.5 h60
  text "ASSEMBLY VARIANT:" at 1153,-434 h60
  text ".VariantName" at 2189,-434 h60
  text "PCB VIEWED FROM TOP SIDE" at -228.5,-655.67 h60
  text "BOARD #:" at 2248,-655.67 h60
  text ".PRJ_Number" at 2793.5,-655.67 h60
  text "REV:" at 3638,-655.67 h60
  text ".PCB_Rev" at 3929.5,-655.67 h60
  text "SVN REV:" at 4476,-655.67 h60
  text ".VersionControl_RevNumber" at 4982,-655.67 h60
  text "IGNORE ->" at -228.5,-858.49 h60
  text "PLOT NAME =" at -228.5,-1064.34 h60
  text ".plot_File_Name" at 577,-1064.34 h60
  text "GENERATED    :" at 2250,-1064.34 h60
  text ".Print_Date" at 3119.5,-1064.34 h60
  text ".Print_Time" at 3848.5,-1064.34 h60
  text "TEXAS INSTRUMENTS" at 5113,-1064.34 h60
M6 Assembly Bottom:
  lines w10: -292.5,-727.33 6309.5,-727.33 ; -290.5,-930.67 6309.5,-930.67 ; 1115.5,-1140.5 1115.5,-937.67 ; 1737.5,-727.33 1737.5,-524 ; 2577.5,-727.33 2577.5,-524 ; 3844.5,-1134 3844.5,-524 ; 4733.5,-1134 6309,-1134 6309,-524 -292.5,-524 -292.5,-1134 2304.5,-1134 6309.5,-1134 6309.5,-524
  text "COMPONENTS MARKED 'DNP' SHOULD NOT BE POPULATED." at 6102,-318 h60
  text ".VariantName" at 5058,-434 h60
  text "ASSEMBLY VARIANT:" at 6097,-434 h60
  text ".VersionControl_RevNumber" at 1035.5,-656.17 h60
  text "SVN REV:" at 1541.5,-656.17 h60
  text ".PCB_Rev" at 2088,-656.17 h60
  text "REV:" at 2379.5,-656.17 h60
  text ".PRJ_Number" at 3224,-656.17 h60
  text "BOARD #:" at 3769.5,-656.17 h60
  text "PCB VIEWED FROM BOTTOM SIDE" at 6246,-656.17 h60
  text "IGNORE ->" at 2547.85,-858.49 h60
  text "TEXAS INSTRUMENTS" at 904.5,-1064.84 h60
  text ".Print_Time" at 2169,-1064.84 h60
  text ".Print_Date" at 2898,-1064.84 h60
  text "GENERATED    :" at 3767.5,-1064.84 h60
  text ".plot_File_Name" at 5440.5,-1064.84 h60
  text "PLOT NAME =" at 6246,-1064.84 h60
M9 Title Sheet:
  drawing of 57 lines, arcs and shapes, not listed
  text "1" at 739.84,8036.5 h70
  text "2" at 3235.5,8036.5 h70
  text "3" at 5724.84,8036.5 h70
  text "4" at 8231.51,8036.5 h70
  text "5" at 10730.5,8036.5 h70
  text "6" at 13235.5,8036.5 h70
  text "A" at -416.5,6893.5 h70
  text "A" at 14383.5,6893.5 h70
  text "B" at -416.5,4513.5 h70
  text "B" at 14383.5,4513.5 h70
  text "C" at -416.5,2138.5 h70
  text "C" at 14383.5,2138.5 h70
  text "PROJECT TITLE:" at 11343.5,277.5 h45
  text ".PRJ_Title" at 11393.5,144.17 h70
  text "DESIGNED FOR:" at 11343.5,-23.5 h45
  text ".PRJ_Customer" at 11393.5,-163.5 h70
  text "D" at -416.5,-231.5 h70
  text "D" at 14383.5,-231.5 h70
  text "FILE NAME:" at 11343.5,-323.5 h45
  text ".PCB_File_Name_No_Path" at 11393.5,-443.5 h70
  text "Texas Instruments (TI) and/or its licensors do not warrant the accuracy or completeness of this specification" at 6374,-605.34 h45
  text "ENGINEER:" at 11343.5,-613.5 h45
  text "LAYOUT BY:" at 12848.5,-613.5 h45
  text "or any information contained therein. TI and/or its licensors do not warrant that this design will meet" at 6329.01,-718 h45
  text ".PRJ_Engineer" at 11393.5,-768.49 h70
  text ".PCB_Layout" at 12899,-768.49 h70
  text "the specifications, will be suitable for your application or fit for any particular purpose, or will operate in" at 6329.01,-830.67 h45
  text ".Layer_Name" at 577,-858.49 h60
  text "ALTIUM DESIGNER VERSION:" at 12848.5,-923.5 h45
  text "an implementation. TI and/or its licensors do not warrant that the design is production worthy. You should" at 6329.01,-943.33 h45
  text "completely validate and test your design implementation to confirm the system functionality for your application." at 6374,-1056 h45
  text ".print_Scale" at 11393.5,-1056.83 h70
  text ".Application_BuildNumber" at 12899,-1056.83 h70
  text "1" at 739.84,-1263.5 h70
  text "2" at 3235.5,-1263.5 h70
  text "3" at 5724.84,-1263.5 h70
  text "4" at 8231.51,-1263.5 h70
  text "5" at 10730.5,-1263.5 h70
  text "6" at 13235.5,-1263.5 h70
M10 Fab Notes:
  drawing of 212 lines, arcs and shapes, not listed
  text "DESIGN INFORMATION" at 12381.02,6810 h60
  text "(REFER ALSO ARRAY/PANEL PROFILING INFORMATION)" at 12019.46,6648.29 h60
  text "BOARD SIZE" at 11333.46,6644 h60
  text "3450MIL" at 11795.78,6516.18 h60
  text "X" at 12301.46,6516.18 h60
  text "4950MIL" at 12532.78,6516.18 h60
  text "Number of Layers :" at 11736.46,6319 h60
  text "2" at 12831.27,6309 h60
  text "MIN. TRACK WIDTH:" at 11736.46,6180 h60
  text "8" at 12832.7,6180 h60
  text "MIL" at 12987.46,6180 h60
  text "MIN. CLEARANCE:" at 11736.46,6048 h60
  text "8" at 12832.7,6048 h60
  text "MIL" at 12987.46,6048 h60
  text "MIN. VIA PAD SIZE:" at 11736.46,5916 h60
  text "24" at 12802.71,5916 h60
  text "MIL" at 12987.46,5916 h60
  text "0.05mm (2MIL)" at 12431.46,5774.29 h60
  text "MINIMUM ANNULAR RING" at 11407.23,5770 h60
  text "EXTERNAL" at 13139.46,5770 h60
  text "PER" at 11607.23,5652 h60
  text "IPC-D-275 CLASS 2 LEVEL C" at 11827.23,5652 h60
  text "MIL, HOLES" at 13315.46,5539.71 h60
  text "+/-" at 12923,5539 h60
  text "+/-" at 13777,5539 h60
  text "REGISTRATION TOLERANCES:" at 11407.23,5534 h60
  text "METAL" at 12607,5534 h60
  text "5" at 13183.2,5534 h60
  text "3" at 14016.2,5534 h60
  text "MIL" at 14132.46,5534 h60
  text "MATERIAL:" at 11332.46,5324.54 h60
  text "FR-4 High Tg" at 12318.9,5184.21 h60
  text "FR-408" at 11753.46,5175.64 h60
  text "X" at 12165.46,5175.64 h60
  text "OTHER" at 13241.46,5175.64 h60
  text "62 MIL (1.6mm) +/-10%" at 12073.56,5012.92 h60
  text "THICKNESS:" at 11407.23,5008.64 h60
  text "X" at 11945.4,5008.64 h60
  text "OTHER" at 13358.46,5008.64 h60
  text "TOLERANCE:" at 11407.23,4850.64 h60
  text "X" at 12246.53,4850.64 h60
  text "ANSI IPC-6012 TYPE 3 CLASS 2" at 12433.48,4850.64 h60
  text "OTHER +/-" at 12433.46,4694.64 h60
  text "BOW & TWIST:" at 11407.23,4537.64 h60
  text "X" at 12246.53,4537.64 h60
  text "ANSI IPC-6012 TYPE 3 CLASS 2" at 12433.48,4537.64 h60
  text "OTHER +/-" at 12433.46,4379.13 h60
  text "COPPER THICKNESS (FINISHED):" at 11332.46,4243.64 h60
  text "1.4MIL (1oz)" at 12212.46,4090.92 h60
  text "2MIL (1.4oz)" at 12979.46,4090.92 h60
  text "2.8MIL (2oz)" at 13706.46,4090.92 h60
  text "OUTER:" at 11689.46,4086.64 h60
  text "X" at 12084,4086 h60
  text "1.4MIL (1oz)" at 12212.46,3933.92 h60
  text "2.8MIL (2oz)" at 12979.46,3933.92 h60
  text "N/A" at 13706,3934.29 h60
  text "INNER SIGNAL:" at 11400.38,3929.64 h60
  text "X" at 12085.42,3929.64 h60
  text "DRILLING:" at 11332.46,3790.64 h60
  text "REFERENCE:" at 11407.23,3673.64 h60
  text "X" at 12055.46,3673.64 h60
  text "AS SHOWN" at 12242.46,3673.64 h60
  text "X" at 12956.46,3673.64 h60
  text "NC_DRILL FILES" at 13093.46,3673.64 h60
  text "PTH MIN COPPER THICKNESS:" at 11407.23,3515.64 h60
  text "X" at 12757.46,3515.64 h60
  text "1MIL" at 12894.46,3515.64 h60
  text "OTHER" at 13391.46,3515.64 h60
  text "BOARD FINISH:" at 11332.46,3356.64 h60
  text "SILKSCREEN:" at 11487.68,3238.64 h60
  text "X" at 12436.46,3238.64 h60
  text "TOP" at 12562.46,3238.64 h60
  text "X" at 12946.46,3238.64 h60
  text "BOTTOM" at 13073.46,3238.64 h60
  text "SILKSCREEN COLOR:" at 11487.68,3071.64 h60
  text "X" at 12435.42,3071.64 h60
  text "WHITE" at 12562.46,3071.64 h60
  text "OTHER" at 13073.46,3071.64 h60
  text "SOLDER RESIST COLOR:" at 11487.68,2901.64 h60
  text "X" at 12055.42,2742.44 h60
  text "GREEN" at 12182.46,2742.44 h60
  text "BLUE" at 12773.46,2742.44 h60
  text "OTHER" at 13311.46,2742.44 h60
  text "IMMERSION GOLD (ENIG)" at 12393.46,2553.92 h60
  text "ENEPIG" at 13731,2550.64 h60
  text "SURFACE FINISH:" at 11332.46,2549.64 h60
  text "X" at 12206.51,2549.64 h60
  text "IMM. TIN/SILVER OR EQUIV" at 11662,2392.64 h60
  text "OTHER" at 13093.46,2392.64 h60
  text "ARRAY/PANEL:" at 11332.46,2213.64 h60
  text "CUT AND TRIM PER MECH LAYER 1" at 12393.46,2209.35 h60
  text "N.C. ROUTE" at 12393.46,2057.64 h60
  text "X" at 13072.46,2057.64 h60
  text "V. SCORE" at 13259.46,2057.64 h60
  text "CERTIFICATION:" at 11332.46,1920.64 h60
  text "MATERIALS AND WORKMANSHIP FOR ALL PCBS" at 12057.46,1920.64 h60
  text "TO MEET OR EXCEED THE REQUIREMENTS OF:" at 12057.46,1822.64 h60
  text "X" at 11683.96,1686.13 h60
  text "ANSI IPC-A-600F CLASS ->" at 11822.96,1686.13 h60
  text "X" at 13462.02,1686.13 h60
  text "2" at 13580.96,1686.14 h60
  text "1" at 13265.96,1684.64 h60
  text "3" at 13934.96,1684.64 h60
  text "X" at 11686.02,1526.64 h60
  text "UL 94V-0" at 11822.96,1526.64 h60
  text "X" at 12498.02,1526.64 h60
  text "RoHS" at 12634.96,1526.64 h60
  text "OTHER" at 13279.36,1526.64 h60
  text "PER ORDER" at 13676.42,1526.64 h60
  text "ADDITIONAL REQUIREMENTS:" at 11332.46,1385.64 h60
  text "MICROSECTION:" at 11407.23,1270.64 h60
  text "YES" at 12312.96,1270.64 h60
  text "REQUIRED" at 13174.46,1114.49 h60
  text "BARE BOARD ELEC. TEST:" at 11407.23,1111.64 h60
  text "NONE" at 12712.96,1111.64 h60
  text "X" at 13047.46,1111.64 h60
  text "PER ORDER" at 13766.46,1111.64 h60
  text "MANUFACTURER'S UL:" at 11407.23,954.64 h60
  text "RAIL" at 12572.96,950.35 h60
  text "METAL" at 13064.77,950.35 h60
  text "X" at 13440,950 h60
  text "SILK" at 13576.46,950.35 h60
  text ".Layer_Name" at 577,-858.49 h60
M11 Gerber Information:
  lines w10: -292,-930.17 6308,-930.17 ; -292,-726.83 6310,-726.83 ; -292,-523.5 -292,-1133.5 3713,-1133.5 6310,-1133.5 6310,-523.5 -291.5,-523.5 -291.5,-1133.5 1284,-1133.5 ; 2173,-1133.5 2173,-523.5 ; 3440,-726.83 3440,-523.5 ; 4280,-726.83 4280,-523.5 ; 4902,-1140 4902,-937.17
  text "ALL ARTWORK VIEWED FROM TOP SIDE" at -228.5,-655.67 h60
  text "BOARD #:" at 2248,-655.67 h60
  text ".PRJ_Number" at 2793.5,-655.67 h60
  text "REV:" at 3638,-655.67 h60
  text ".PCB_Rev" at 3929.5,-655.67 h60
  text "SVN REV:" at 4476,-655.67 h60
  text ".VersionControl_RevNumber" at 4982,-655.67 h60
  text "LAYER NAME =" at -228.5,-858.49 h60
  text "PLOT NAME =" at -228.5,-1064.34 h60
  text ".plot_File_Name" at 577,-1064.34 h60
  text "GENERATED    :" at 2250,-1064.34 h60
  text ".Print_Date" at 3119.5,-1064.34 h60
  text ".Print_Time" at 3848.5,-1064.34 h60
  text "TEXAS INSTRUMENTS" at 5113,-1064.34 h60
M12 Stackup:
  lines w6: 11360,7460 13910,7460 ; 11360,7564.4 13910,7564.4 ; 11300,6975 ccw(c11334,6975) 11334,6941 13936,6941 ccw(c13936,6975) 13970,6975 13970,7681 ccw(c13936,7681) 13936,7715 11334,7715 ccw(c11334,7681) 11300,7681 11300,6975
  text "The Stackup Legend below this is static." at 11605.5,7874.5 h60
  text "If you change the stackup, update the Legend." at 11615.5,7784.5 h60
  text "Layer Stack Up Detail for: Ref_Design.PcbDoc" at 11360,7597.1 h57
  text "Layer" at 11360,7525.4 h24
  text "Gerber" at 12255.81,7525.4 h24
  text "Copper" at 12819.33,7525.4 h24
  text "Dielectric" at 13422.04,7525.4 h24
  text "Name" at 11360,7477.4 h24
  text "Document" at 12255.81,7477.4 h24
  text "Thickness" at 12819.33,7477.4 h24
  text "Material" at 13422.04,7477.4 h24
  text "Top Solder Mask" at 11360,7384.44 h34
  text "(.GTS)" at 12255.81,7384.44 h34
  text "Solder Resist" at 13422.04,7384.44 h34
  text "Top Layer" at 11360,7287.69 h34
  text "(.GTL)" at 12255.81,7287.69 h34
  text "1.4mil" at 12819.33,7287.69 h34
  text "FR-4" at 13422.04,7239.31 h34
  text "Bottom Layer" at 11360,7190.94 h34
  text "(.GBL)" at 12255.81,7190.94 h34
  text "1.4mil" at 12819.33,7190.94 h34
  text "Bottom Solder Mask" at 11360,7094.19 h34
  text "(.GBS)" at 12255.81,7094.19 h34
  text "Solder Resist" at 13422.04,7094.19 h34
  text ".Layer_Name" at 577,-858.49 h60
M13 Component Bodies Top:
  text ".Layer_Name" at 577,-858.49 h60
M14 Component Bodies Bottom:
  text ".Layer_Name" at 577,-858.49 h60
M15 Courtyards Top:
  text ".Layer_Name" at 577,-858.49 h60
M16 Courtyards Bottom:
  text ".Layer_Name" at 577,-858.49 h60
Drill Drawing:
  text ".legend" at 5122.5,725.5 h60
  text "Drill Table" at 5147.5,540.5 h60
  text ".Layer_Name" at 577,-858.49 h60

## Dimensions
10,1120 to 0,-10 on M2 Board Dimensions
1780,-120 to 10,1120 on M2 Board Dimensions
